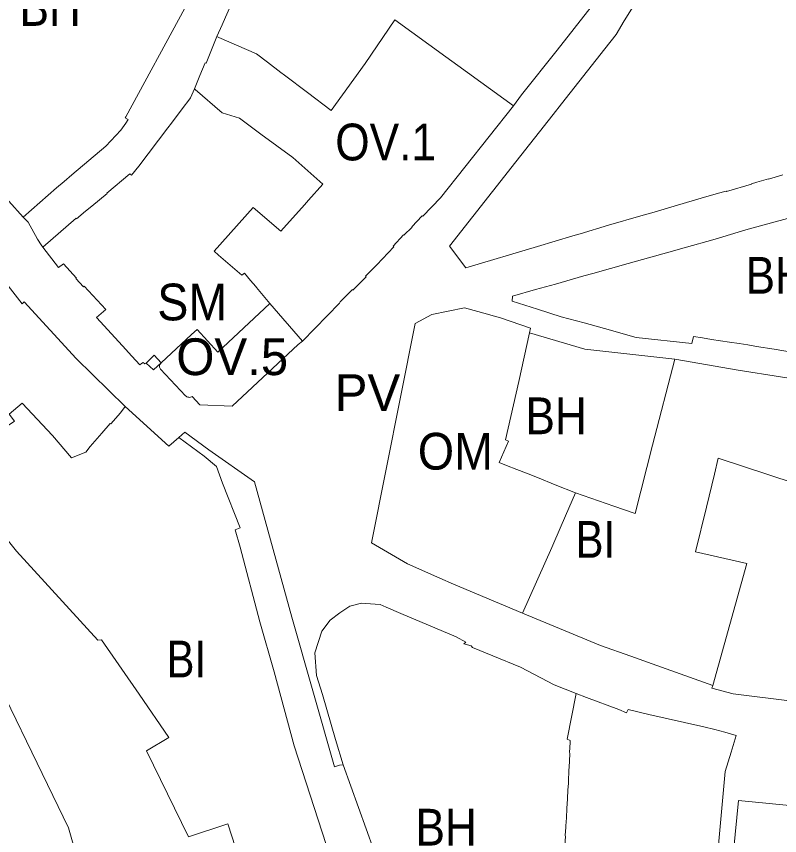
# Model space of a CAD drawing. Extents: x -650451 to -642268, y -1075216 to -1066610.
# Drawn here: x -646868 to -646618.6, y -1071143.1 to -1070875.5 of the extents above; entities that cross this region are included whole.
import ezdxf

# ---------------------------------------------------------------- set-up
doc = ezdxf.new("R2010")
doc.units = 0
doc.header["$LTSCALE"] = 4.8
for name, color, linetype, lineweight in [('1', 7, 'Continuous', 13), ('11', 7, 'Continuous', 13), ('12', 7, 'Continuous', 13), ('15', 7, 'Continuous', 13), ('18', 7, 'Continuous', 13), ('2', 7, 'Continuous', 13), ('30', 7, 'Continuous', 13), ('43', 7, 'Continuous', 13)]:
    doc.layers.add(name, color=color, linetype=linetype, lineweight=lineweight)
doc.layers.add('62', color=7, linetype='Continuous')

msp = doc.modelspace()

# ---------------------------------------------------------------- linework, layer by layer
at = {"layer": '1'}
for points in [[(-646812.95, -1070872.84), (-646832.23, -1070908.37), (-646832.4, -1070908.62), (-646831.49, -1070909.26), (-646832.25, -1070910.39), (-646833.83, -1070912.75), (-646838.79, -1070917.88), (-646849.85, -1070927.33), (-646852.33, -1070929.44), (-646854.84, -1070931.57), (-646865.78, -1070941.08)], [(-646865.78, -1070941.08), (-646870.44, -1070935.85), (-646879.26, -1070925.81), (-646882.88, -1070921.68), (-646883.57, -1070922.28), (-646884.99, -1070920.6), (-646885.27, -1070920.29), (-646884.61, -1070919.71), (-646889.41, -1070914.22), (-646889.61, -1070914), (-646891.81, -1070911.53)], [(-646614.7, -1070985.2), (-646620.38, -1070984.27), (-646626.1, -1070983.33), (-646628.91, -1070982.87), (-646631.81, -1070982.39), (-646634.97, -1070981.91), (-646640.81, -1070981.03), (-646643.77, -1070980.58), (-646646.72, -1070980.14), (-646647.31, -1070982.43), (-646665.45, -1070980.38), (-646675.83, -1070977.44), (-646682.42, -1070975.63), (-646689.96, -1070973.64), (-646697.66, -1070971.16), (-646705.93, -1070968.51), (-646705.91, -1070966.92), (-646698.32, -1070964.78), (-646691.85, -1070962.95), (-646682.51, -1070960.32), (-646682.52, -1070960.27), (-646679.66, -1070959.5), (-646668.1, -1070956.26), (-646654.77, -1070952.52), (-646649.8, -1070951.12), (-646639.59, -1070948.26), (-646629.66, -1070945.21), (-646586.78, -1070933.58)], [(-646685.32, -1071031.21), (-646691.92, -1071028.54), (-646697.71, -1071026.2), (-646701.29, -1071024.78), (-646704.45, -1071023.54), (-646707.84, -1071022.2), (-646710.22, -1071021.22), (-646707.16, -1071014.27), (-646708.13, -1071013.84), (-646703.84, -1070994.76), (-646700.3, -1070978.95)], [(-646700.3, -1070978.95), (-646682.18, -1070984.24), (-646652.84, -1070987.5)], [(-646652.84, -1070987.5), (-646660.08, -1071015.58), (-646665.82, -1071037.86), (-646672.76, -1071035.57), (-646685.32, -1071031.21)], [(-646761.14, -1071120.05), (-646763.65, -1071111.7), (-646767.99, -1071096.99), (-646769.87, -1071090.86), (-646770.44, -1071083.38), (-646768.14, -1071076.35), (-646765.4, -1071072.79), (-646762.26, -1071070.38), (-646758.97, -1071068.19), (-646755.17, -1071067.15), (-646753.91, -1071067.28), (-646749.06, -1071067.63), (-646747.09, -1071068.47), (-646742.31, -1071070.55), (-646724.24, -1071078.24), (-646721.09, -1071079.94), (-646721.75, -1071080.46), (-646719.35, -1071081.17), (-646718.93, -1071081.64), (-646712.28, -1071084.44), (-646703.22, -1071088.08), (-646692.29, -1071093.84), (-646685.11, -1071096.75)], [(-646685.11, -1071096.75), (-646688.05, -1071111.58), (-646687.05, -1071112.07), (-646687.07, -1071112.75), (-646687.18, -1071116), (-646687.13, -1071116.19), (-646687.27, -1071118.9), (-646687.44, -1071122.04), (-646687.61, -1071125.14), (-646687.53, -1071126.08), (-646687.77, -1071128.18), (-646687.93, -1071131.08), (-646688.1, -1071134.22), (-646688.26, -1071137.27), (-646688.47, -1071139.89), (-646688.43, -1071140.41), (-646688.69, -1071143.09), (-646688.59, -1071143.43), (-646690.94, -1071176.2), (-646699.42, -1071163.53), (-646731.92, -1071183.91)], [(-646731.92, -1071183.91), (-646738.95, -1071172.12), (-646742.79, -1071164.96), (-646751.14, -1071147.83), (-646761.14, -1071120.05)]]:
    msp.add_lwpolyline(points, dxfattribs=at)
at = {"layer": '11'}
for points in [[(-646802.42, -1070882.15), (-646801.87, -1070882.39), (-646789.49, -1070887.76), (-646785.97, -1070890.46), (-646781.53, -1070893.85), (-646780.41, -1070894.71), (-646772.89, -1070900.37), (-646765.09, -1070906.26), (-646753.96, -1070890.92), (-646744.29, -1070876.64), (-646727.65, -1070888.7), (-646723.75, -1070891.53), (-646705.57, -1070904.71)], [(-646809.74, -1070899.18), (-646808.03, -1070894.8), (-646806.29, -1070890.74), (-646806.01, -1070890.86), (-646802.42, -1070882.15)], [(-646785.1, -1070969.35), (-646789.51, -1070964.1), (-646789.77, -1070963.8), (-646791.42, -1070961.82), (-646793.42, -1070959.44), (-646794.34, -1070960.06), (-646801.88, -1070953.52), (-646803.38, -1070952.23), (-646790.65, -1070937.91), (-646781.61, -1070945.71), (-646773.84, -1070937.13), (-646772.48, -1070935.59), (-646767.79, -1070930.3), (-646777.6, -1070921.63), (-646788.07, -1070913.98), (-646795.1, -1070908.82), (-646800.71, -1070907.07), (-646809.52, -1070899.38), (-646809.74, -1070899.18)], [(-646705.57, -1070904.71), (-646729.43, -1070934.78), (-646735.16, -1070940.84), (-646735.4, -1070940.66), (-646738.78, -1070944.31), (-646738.67, -1070944.39), (-646741.39, -1070946.95), (-646741.49, -1070946.87), (-646744.88, -1070950.57), (-646744.65, -1070950.76), (-646750.23, -1070956.64), (-646753.94, -1070960.44), (-646753.73, -1070960.66), (-646757.98, -1070964.99), (-646758.19, -1070964.78), (-646762.13, -1070968.76), (-646762.44, -1070969.18), (-646774.48, -1070981.6), (-646785.1, -1070969.35)], [(-646820.65, -1070988.7), (-646810.75, -1070979.48), (-646808.94, -1070977.8), (-646802.17, -1070985.18), (-646786.88, -1070970.99), (-646785.1, -1070969.35), (-646774.48, -1070981.6)], [(-646774.48, -1070981.6), (-646775.94, -1070982.72), (-646775.91, -1070982.75), (-646797.46, -1071002.84), (-646807.98, -1071002.37), (-646810.48, -1070999.7), (-646810.737, -1070999.834), (-646811.025, -1070999.928), (-646811.333, -1070999.974), (-646811.649, -1070999.967), (-646811.958, -1070999.905), (-646812.249, -1070999.792), (-646812.508, -1070999.637), (-646812.73, -1070999.45), (-646820.87, -1070990.72), (-646821, -1070990.539), (-646821.104, -1070990.33), (-646821.172, -1070990.101), (-646821.2, -1070989.859), (-646821.186, -1070989.616), (-646821.131, -1070989.382), (-646821.04, -1070989.168), (-646820.92, -1070988.98), (-646820.65, -1070988.7)], [(-646825.54, -1070988.78), (-646822.97, -1070986.2), (-646820.65, -1070988.7)], [(-646820.65, -1070988.7), (-646823.14, -1070991.02), (-646825.54, -1070988.78)]]:
    msp.add_lwpolyline(points, dxfattribs=at)
at = {"layer": '12'}
for points in [[(-646702.6, -1071070.42), (-646725.18, -1071061.03), (-646729.65, -1071059.08), (-646740.15, -1071054.37), (-646751.894, -1071047.444), (-646737.716, -1070975.84), (-646732.26, -1070972.9), (-646721.5, -1070970.69), (-646714.02, -1070972.79), (-646712.21, -1070973.32), (-646709.82, -1070974.01), (-646699.94, -1070977.39), (-646700.3, -1070978.95)], [(-646700.3, -1070978.95), (-646703.84, -1070994.76), (-646708.13, -1071013.84), (-646707.16, -1071014.27), (-646710.22, -1071021.22), (-646707.84, -1071022.2), (-646704.45, -1071023.54), (-646701.29, -1071024.78), (-646697.71, -1071026.2), (-646691.92, -1071028.54), (-646685.32, -1071031.21)], [(-646685.32, -1071031.21), (-646687.44, -1071036.14), (-646689.94, -1071041.93), (-646693.01, -1071049.06), (-646702.6, -1071070.42)]]:
    msp.add_lwpolyline(points, dxfattribs=at)
at = {"layer": '15'}
for points in [[(-646749.54, -1070811.66), (-646768.98, -1070804.68), (-646771.01, -1070809.56), (-646777.89, -1070825.37), (-646778.21, -1070826.17), (-646768.86, -1070830.4), (-646768.51, -1070829.62), (-646764.25, -1070831.74), (-646771.9, -1070844.66), (-646783.67, -1070839.03), (-646786.32, -1070844.88), (-646793.57, -1070861.9), (-646793.61, -1070862.05), (-646793.79, -1070861.97), (-646794.08, -1070862.59), (-646797.04, -1070869.8), (-646799.63, -1070875.74), (-646800.75, -1070878.32), (-646802.42, -1070882.15)], [(-646661.55, -1070864.35), (-646669.35, -1070877.04), (-646672.04, -1070881.41), (-646675.72, -1070886.17), (-646689.83, -1070904.06), (-646692.61, -1070907.6), (-646704.78, -1070923.08), (-646726.47, -1070950.62), (-646721.07, -1070957.7), (-646697.64, -1070950.68), (-646686.14, -1070947.24), (-646683.8, -1070946.58), (-646674.5, -1070943.76), (-646663.97, -1070940.71), (-646659.58, -1070939.44), (-646651.9, -1070937.18), (-646644.2, -1070934.92), (-646642.33, -1070934.41), (-646639.69, -1070933.62), (-646638.98, -1070933.41), (-646635.99, -1070932.6), (-646635.95, -1070932.74), (-646627.72, -1070930.35), (-646627.77, -1070930.19), (-646625.98, -1070929.65), (-646622.24, -1070928.56), (-646622.2, -1070928.69), (-646617.52, -1070927.31)], [(-646865.78, -1070941.08), (-646854.84, -1070931.57), (-646852.33, -1070929.44), (-646849.85, -1070927.33), (-646838.79, -1070917.88), (-646833.83, -1070912.75), (-646832.25, -1070910.39), (-646831.49, -1070909.26), (-646832.4, -1070908.62), (-646832.23, -1070908.37), (-646812.95, -1070872.84)], [(-646705.57, -1070904.71), (-646702.9, -1070901.14), (-646691.31, -1070886.57), (-646680.19, -1070872.4)], [(-646802.42, -1070882.15), (-646806.01, -1070890.86), (-646806.29, -1070890.74), (-646808.03, -1070894.8), (-646809.74, -1070899.18)], [(-646809.74, -1070899.18), (-646811.06, -1070902.11), (-646811.97, -1070903.31), (-646813.16, -1070904.89), (-646817.3, -1070910.37), (-646818.46, -1070911.9), (-646827.91, -1070924.42), (-646830.32, -1070927.42), (-646830.88, -1070926.96), (-646838.38, -1070933.3), (-646838.28, -1070933.42), (-646843.29, -1070937.51), (-646845.42, -1070939.14), (-646848.31, -1070941.62), (-646848.48, -1070941.43), (-646859.36, -1070950.91)], [(-646774.48, -1070981.6), (-646762.44, -1070969.18), (-646762.13, -1070968.76), (-646758.19, -1070964.78), (-646757.98, -1070964.99), (-646753.73, -1070960.66), (-646753.94, -1070960.44), (-646750.23, -1070956.64), (-646744.65, -1070950.76), (-646744.88, -1070950.57), (-646741.49, -1070946.87), (-646741.39, -1070946.95), (-646738.67, -1070944.39), (-646738.78, -1070944.31), (-646735.4, -1070940.66), (-646735.16, -1070940.84), (-646729.43, -1070934.78), (-646705.57, -1070904.71)], [(-646891.81, -1070911.53), (-646889.61, -1070914), (-646889.41, -1070914.22), (-646884.61, -1070919.71), (-646885.27, -1070920.29), (-646884.99, -1070920.6), (-646883.57, -1070922.28), (-646882.88, -1070921.68), (-646879.26, -1070925.81), (-646870.44, -1070935.85), (-646865.78, -1070941.08)], [(-646586.78, -1070933.58), (-646629.66, -1070945.21), (-646639.59, -1070948.26), (-646649.8, -1070951.12), (-646654.77, -1070952.52), (-646668.1, -1070956.26), (-646679.66, -1070959.5), (-646682.52, -1070960.27), (-646682.51, -1070960.32), (-646691.85, -1070962.95), (-646698.32, -1070964.78), (-646705.91, -1070966.92), (-646705.93, -1070968.51), (-646697.66, -1070971.16), (-646689.96, -1070973.64), (-646682.42, -1070975.63), (-646675.83, -1070977.44), (-646665.45, -1070980.38), (-646647.31, -1070982.43), (-646646.72, -1070980.14), (-646643.77, -1070980.58), (-646640.81, -1070981.03), (-646634.97, -1070981.91), (-646631.81, -1070982.39), (-646628.91, -1070982.87), (-646626.1, -1070983.33), (-646620.38, -1070984.27), (-646614.7, -1070985.2)], [(-646865.78, -1070941.08), (-646864.13, -1070942.79), (-646861.06, -1070948.33), (-646859.9, -1070950.19), (-646859.36, -1070950.91)], [(-646859.36, -1070950.91), (-646859.9, -1070950.19), (-646861.06, -1070948.33), (-646864.13, -1070942.79), (-646865.78, -1070941.08)], [(-646859.36, -1070950.91), (-646854.22, -1070957.58), (-646852.62, -1070956.4), (-646848.34, -1070961), (-646848.53, -1070961.2), (-646846.03, -1070963.89), (-646845.82, -1070963.67), (-646838.79, -1070971.27), (-646841.8, -1070973.84), (-646833.28, -1070983.12), (-646833.34, -1070983.18), (-646830.27, -1070986.54), (-646827.59, -1070989.31), (-646827.07, -1070988.88), (-646826.5, -1070988.61), (-646825.95, -1070989.07), (-646825.54, -1070988.78)], [(-646832.43, -1071002.96), (-646848.44, -1070987.31), (-646865.43, -1070968.8), (-646866.04, -1070969.39), (-646878.42, -1070953.74), (-646887.09, -1070959.23), (-646901.2, -1070965.38)], [(-646700.3, -1070978.95), (-646699.94, -1070977.39), (-646709.82, -1070974.01), (-646712.21, -1070973.32), (-646714.02, -1070972.79), (-646721.5, -1070970.69), (-646732.26, -1070972.9), (-646737.716, -1070975.84), (-646751.894, -1071047.444), (-646740.15, -1071054.37), (-646729.65, -1071059.08), (-646725.18, -1071061.03), (-646702.6, -1071070.42)], [(-646652.84, -1070987.5), (-646682.18, -1070984.24), (-646700.3, -1070978.95)], [(-646820.65, -1070988.7), (-646820.92, -1070988.98), (-646821.04, -1070989.168), (-646821.131, -1070989.382), (-646821.186, -1070989.616), (-646821.2, -1070989.859), (-646821.172, -1070990.101), (-646821.104, -1070990.33), (-646821, -1070990.539), (-646820.87, -1070990.72), (-646812.73, -1070999.45), (-646812.508, -1070999.637), (-646812.249, -1070999.792), (-646811.958, -1070999.905), (-646811.649, -1070999.967), (-646811.333, -1070999.974), (-646811.025, -1070999.928), (-646810.737, -1070999.834), (-646810.48, -1070999.7), (-646807.98, -1071002.37), (-646797.46, -1071002.84), (-646775.91, -1070982.75), (-646775.94, -1070982.72), (-646774.48, -1070981.6)], [(-646825.54, -1070988.78), (-646823.14, -1070991.02), (-646820.65, -1070988.7)], [(-646589.68, -1070997.52), (-646593.31, -1070997.01), (-646604.46, -1070995.43), (-646632.16, -1070991.11), (-646652.84, -1070987.5)], [(-646814.9, -1071013.09), (-646818.15, -1071015.95), (-646832.43, -1071002.96)], [(-646814.9, -1071013.09), (-646812.98, -1071011.4), (-646805.07, -1071017.16), (-646790.2, -1071027.54), (-646777.99, -1071071.73), (-646764, -1071120.65), (-646762.4, -1071120.15), (-646761.14, -1071120.05)], [(-646761.14, -1071120.05), (-646762.4, -1071120.15), (-646764, -1071120.65), (-646777.99, -1071071.73), (-646790.2, -1071027.54), (-646805.07, -1071017.16), (-646812.98, -1071011.4), (-646814.9, -1071013.09)], [(-646765.47, -1071150.02), (-646777.21, -1071113.75), (-646783.79, -1071089.61), (-646788.42, -1071073.28), (-646794.9, -1071048.94), (-646796.51, -1071043.25), (-646794.85, -1071042.64), (-646800.59, -1071028.03), (-646802.63, -1071022.55), (-646806.6, -1071019.18), (-646814.9, -1071013.09)], [(-646685.11, -1071096.75), (-646692.29, -1071093.84), (-646703.22, -1071088.08), (-646712.28, -1071084.44), (-646718.93, -1071081.64), (-646719.35, -1071081.17), (-646721.75, -1071080.46), (-646721.09, -1071079.94), (-646724.24, -1071078.24), (-646742.31, -1071070.55), (-646747.09, -1071068.47), (-646749.06, -1071067.63), (-646753.91, -1071067.28), (-646755.17, -1071067.15), (-646758.97, -1071068.19), (-646762.26, -1071070.38), (-646765.4, -1071072.79), (-646768.14, -1071076.35), (-646770.44, -1071083.38), (-646769.87, -1071090.86), (-646767.99, -1071096.99), (-646763.65, -1071111.7), (-646761.14, -1071120.05)], [(-646702.6, -1071070.42), (-646677.12, -1071081.01), (-646667.23, -1071084.54), (-646660.21, -1071087), (-646640.4, -1071094.05)], [(-646640.4, -1071094.05), (-646640.74, -1071094.97), (-646633.75, -1071096.82), (-646613.56, -1071099.28), (-646611.08, -1071099.83), (-646579.09, -1071106.84)], [(-646638.51, -1071199.81), (-646642.57, -1071199.48), (-646643.19, -1071199.42), (-646641.56, -1071181.08), (-646638.63, -1071147.31), (-646636.35, -1071122.22), (-646634.44, -1071115.83), (-646632.81, -1071110.48), (-646636.53, -1071109.37), (-646639.79, -1071108.48), (-646643.39, -1071107.55), (-646661.28, -1071103.62), (-646668.07, -1071101.93), (-646668.62, -1071103.01), (-646671.11, -1071101.98), (-646681.64, -1071098.05), (-646685.11, -1071096.75)], [(-646761.14, -1071120.05), (-646751.14, -1071147.83), (-646742.79, -1071164.96), (-646738.95, -1071172.12), (-646731.92, -1071183.91)], [(-646600.68, -1071203.07), (-646596.74, -1071149.51), (-646596.32, -1071145.78), (-646595.94, -1071142.45), (-646595.56, -1071139.02), (-646595.24, -1071135.46), (-646601.97, -1071134.57), (-646631.97, -1071131.64), (-646633.62, -1071148.36), (-646638.24, -1071196.41), (-646638.51, -1071199.81)]]:
    msp.add_lwpolyline(points, dxfattribs=at)
at = {"layer": '18'}
for points in [[(-646859.36, -1070950.91), (-646848.48, -1070941.43), (-646848.31, -1070941.62), (-646845.42, -1070939.14), (-646843.29, -1070937.51), (-646838.28, -1070933.42), (-646838.38, -1070933.3), (-646830.88, -1070926.96), (-646830.32, -1070927.42), (-646827.91, -1070924.42), (-646818.46, -1070911.9), (-646817.3, -1070910.37), (-646813.16, -1070904.89), (-646811.97, -1070903.31), (-646811.06, -1070902.11), (-646809.74, -1070899.18)], [(-646809.74, -1070899.18), (-646809.52, -1070899.38), (-646800.71, -1070907.07), (-646795.1, -1070908.82), (-646788.07, -1070913.98), (-646777.6, -1070921.63), (-646767.79, -1070930.3), (-646772.48, -1070935.59), (-646773.84, -1070937.13), (-646781.61, -1070945.71), (-646790.65, -1070937.91), (-646803.38, -1070952.23), (-646801.88, -1070953.52), (-646794.34, -1070960.06), (-646793.42, -1070959.44), (-646791.42, -1070961.82), (-646789.77, -1070963.8), (-646789.51, -1070964.1), (-646785.1, -1070969.35)], [(-646825.54, -1070988.78), (-646825.95, -1070989.07), (-646826.5, -1070988.61), (-646827.07, -1070988.88), (-646827.59, -1070989.31), (-646830.27, -1070986.54), (-646833.34, -1070983.18), (-646833.28, -1070983.12), (-646841.8, -1070973.84), (-646838.79, -1070971.27), (-646845.82, -1070963.67), (-646846.03, -1070963.89), (-646848.53, -1070961.2), (-646848.34, -1070961), (-646852.62, -1070956.4), (-646854.22, -1070957.58), (-646859.36, -1070950.91)], [(-646901.2, -1070965.38), (-646887.09, -1070959.23), (-646878.42, -1070953.74), (-646866.04, -1070969.39), (-646865.43, -1070968.8), (-646848.44, -1070987.31), (-646832.43, -1071002.96)], [(-646785.1, -1070969.35), (-646786.88, -1070970.99), (-646802.17, -1070985.18), (-646808.94, -1070977.8), (-646810.75, -1070979.48), (-646820.65, -1070988.7)], [(-646820.65, -1070988.7), (-646822.97, -1070986.2), (-646825.54, -1070988.78)], [(-646832.43, -1071002.96), (-646833.9, -1071005.08), (-646837.1, -1071008.63), (-646837.34, -1071008.47), (-646840.08, -1071011.65), (-646843.86, -1071016.05), (-646845.29, -1071017.89), (-646849.95, -1071019.76), (-646856.12, -1071012.42), (-646866.1, -1071001.89), (-646870.37, -1071005.49), (-646868.6, -1071007.71), (-646873.04, -1071010.77), (-646872.61, -1071011.55), (-646873.25, -1071011.98), (-646873.79, -1071011.16), (-646877.28, -1071013.64), (-646876.95, -1071014.34), (-646878.47, -1071015.58), (-646879, -1071014.96), (-646889.15, -1071022.27)]]:
    msp.add_lwpolyline(points, dxfattribs=at)
at = {"layer": '2'}
for points in [[(-646802.42, -1070882.15), (-646800.75, -1070878.32), (-646799.63, -1070875.74), (-646797.04, -1070869.8), (-646794.08, -1070862.59), (-646793.79, -1070861.97), (-646793.61, -1070862.05), (-646793.57, -1070861.9), (-646786.32, -1070844.88), (-646783.67, -1070839.03), (-646771.9, -1070844.66), (-646764.25, -1070831.74), (-646768.51, -1070829.62), (-646768.86, -1070830.4), (-646778.21, -1070826.17), (-646777.89, -1070825.37), (-646771.01, -1070809.56), (-646768.98, -1070804.68), (-646749.54, -1070811.66)], [(-646617.52, -1070927.31), (-646622.2, -1070928.69), (-646622.24, -1070928.56), (-646625.98, -1070929.65), (-646627.77, -1070930.19), (-646627.72, -1070930.35), (-646635.95, -1070932.74), (-646635.99, -1070932.6), (-646638.98, -1070933.41), (-646639.69, -1070933.62), (-646642.33, -1070934.41), (-646644.2, -1070934.92), (-646651.9, -1070937.18), (-646659.58, -1070939.44), (-646663.97, -1070940.71), (-646674.5, -1070943.76), (-646683.8, -1070946.58), (-646686.14, -1070947.24), (-646697.64, -1070950.68), (-646721.07, -1070957.7), (-646726.47, -1070950.62), (-646704.78, -1070923.08), (-646692.61, -1070907.6), (-646689.83, -1070904.06), (-646675.72, -1070886.17), (-646672.04, -1070881.41), (-646669.35, -1070877.04), (-646661.55, -1070864.35)], [(-646680.19, -1070872.4), (-646691.31, -1070886.57), (-646702.9, -1070901.14), (-646705.57, -1070904.71)], [(-646705.57, -1070904.71), (-646723.75, -1070891.53), (-646727.65, -1070888.7), (-646744.29, -1070876.64), (-646753.96, -1070890.92), (-646765.09, -1070906.26), (-646772.89, -1070900.37), (-646780.41, -1070894.71), (-646781.53, -1070893.85), (-646785.97, -1070890.46), (-646789.49, -1070887.76), (-646801.87, -1070882.39), (-646802.42, -1070882.15)], [(-646685.32, -1071031.21), (-646672.76, -1071035.57), (-646665.82, -1071037.86), (-646660.08, -1071015.58), (-646652.84, -1070987.5)], [(-646652.84, -1070987.5), (-646632.16, -1070991.11), (-646604.46, -1070995.43), (-646593.31, -1070997.01), (-646589.68, -1070997.52)], [(-646589.68, -1070997.52), (-646590.25, -1070999.85), (-646591.8, -1071006.27), (-646594.02, -1071015.4), (-646595.64, -1071022.05), (-646598.32, -1071033.1), (-646613.79, -1071028.02), (-646638.64, -1071019.8), (-646639.89, -1071025.07), (-646642.45, -1071035.84), (-646646.07, -1071050.42), (-646629.25, -1071054.25), (-646640.4, -1071094.05)], [(-646889.15, -1071022.27), (-646879, -1071014.96), (-646878.47, -1071015.58), (-646876.95, -1071014.34), (-646877.28, -1071013.64), (-646873.79, -1071011.16), (-646873.25, -1071011.98), (-646872.61, -1071011.55), (-646873.04, -1071010.77), (-646868.6, -1071007.71), (-646870.37, -1071005.49), (-646866.1, -1071001.89), (-646856.12, -1071012.42), (-646849.95, -1071019.76), (-646845.29, -1071017.89), (-646843.86, -1071016.05), (-646840.08, -1071011.65), (-646837.34, -1071008.47), (-646837.1, -1071008.63), (-646833.9, -1071005.08), (-646832.43, -1071002.96)], [(-646832.43, -1071002.96), (-646818.15, -1071015.95), (-646814.9, -1071013.09)], [(-646814.9, -1071013.09), (-646806.6, -1071019.18), (-646802.63, -1071022.55), (-646800.59, -1071028.03), (-646794.85, -1071042.64), (-646796.51, -1071043.25), (-646794.9, -1071048.94), (-646788.42, -1071073.28), (-646783.79, -1071089.61), (-646777.21, -1071113.75), (-646765.47, -1071150.02)], [(-646795.19, -1071150.7), (-646798.88, -1071139.24), (-646811.73, -1071143.52), (-646825.46, -1071115.49), (-646818.14, -1071111.05), (-646827.84, -1071096.9), (-646840.19, -1071079.22), (-646841.37, -1071079.25), (-646867.95, -1071050.27), (-646877.15, -1071038.8), (-646889.15, -1071022.27)], [(-646702.6, -1071070.42), (-646693.01, -1071049.06), (-646689.94, -1071041.93), (-646687.44, -1071036.14), (-646685.32, -1071031.21)], [(-646640.4, -1071094.05), (-646660.21, -1071087), (-646667.23, -1071084.54), (-646677.12, -1071081.01), (-646702.6, -1071070.42)], [(-646731.92, -1071183.91), (-646699.42, -1071163.53), (-646690.94, -1071176.2), (-646688.59, -1071143.43), (-646688.69, -1071143.09), (-646688.43, -1071140.41), (-646688.47, -1071139.89), (-646688.26, -1071137.27), (-646688.1, -1071134.22), (-646687.93, -1071131.08), (-646687.77, -1071128.18), (-646687.53, -1071126.08), (-646687.61, -1071125.14), (-646687.44, -1071122.04), (-646687.27, -1071118.9), (-646687.13, -1071116.19), (-646687.18, -1071116), (-646687.07, -1071112.75), (-646687.05, -1071112.07), (-646688.05, -1071111.58), (-646685.11, -1071096.75)], [(-646685.11, -1071096.75), (-646681.64, -1071098.05), (-646671.11, -1071101.98), (-646668.62, -1071103.01), (-646668.07, -1071101.93), (-646661.28, -1071103.62), (-646643.39, -1071107.55), (-646639.79, -1071108.48), (-646636.53, -1071109.37), (-646632.81, -1071110.48), (-646634.44, -1071115.83), (-646636.35, -1071122.22), (-646638.63, -1071147.31), (-646641.56, -1071181.08), (-646643.19, -1071199.42), (-646642.57, -1071199.48), (-646638.51, -1071199.81), (-646600.68, -1071203.07)]]:
    msp.add_lwpolyline(points, dxfattribs=at)
at = {"layer": '30'}
for points in [[(-646640.4, -1071094.05), (-646629.25, -1071054.25), (-646646.07, -1071050.42), (-646642.45, -1071035.84), (-646639.89, -1071025.07), (-646638.64, -1071019.8), (-646613.79, -1071028.02), (-646598.32, -1071033.1), (-646595.64, -1071022.05), (-646594.02, -1071015.4), (-646591.8, -1071006.27), (-646590.25, -1070999.85), (-646589.68, -1070997.52)], [(-646579.09, -1071106.84), (-646611.08, -1071099.83), (-646613.56, -1071099.28), (-646633.75, -1071096.82), (-646640.74, -1071094.97), (-646640.4, -1071094.05)]]:
    msp.add_lwpolyline(points, dxfattribs=at)
msp.add_lwpolyline([(-646638.51, -1071199.81), (-646638.24, -1071196.41), (-646633.62, -1071148.36), (-646631.97, -1071131.64), (-646601.97, -1071134.57), (-646595.24, -1071135.46), (-646595.56, -1071139.02), (-646595.94, -1071142.45), (-646596.32, -1071145.78), (-646596.74, -1071149.51), (-646600.68, -1071203.07)], close=True, dxfattribs=at)
at = {"layer": '43'}
for points in [[(-646889.15, -1071022.27), (-646877.15, -1071038.8), (-646867.95, -1071050.27), (-646841.37, -1071079.25), (-646840.19, -1071079.22), (-646827.84, -1071096.9), (-646818.14, -1071111.05), (-646825.46, -1071115.49), (-646811.73, -1071143.52), (-646798.88, -1071139.24), (-646795.19, -1071150.7)], [(-646854.49, -1071185.87), (-646852.86, -1071183.98), (-646848.58, -1071163.95), (-646845.39, -1071159.98), (-646850.93, -1071140.54), (-646881.89, -1071077.03), (-646890.12, -1071069.67)]]:
    msp.add_lwpolyline(points, dxfattribs=at)

# ---------------------------------------------------------------- texts
at = {"layer": '62'}
for s, width, p in [('BH', 0.9, (-646866.957, -1070878.632)), ('OV.1', 0.9, (-646763.769, -1070922.57)), ('BH', 0.9, (-646629.701, -1070966.132)), ('SM', 0.95, (-646821.938, -1070974.828)), ('BH', 0.9, (-646701.627, -1071012.009)), ('OM', 0.95, (-646736.796, -1071023.577)), ('BI', 0.85, (-646685.229, -1071052.385)), ('BI', 0.85, (-646818.886, -1071091.455)), ('BH', 0.9, (-646737.56, -1071146.38))]:
    msp.add_text(s, height=12, dxfattribs=dict(at, width=width)).set_placement(p)
for s, p in [('OV.5', (-646815.739, -1070992.709)), ('PV', (-646763.943, -1071004.419))]:
    msp.add_text(s, height=12, dxfattribs=at).set_placement(p)

doc.saveas('drawing.dxf')
